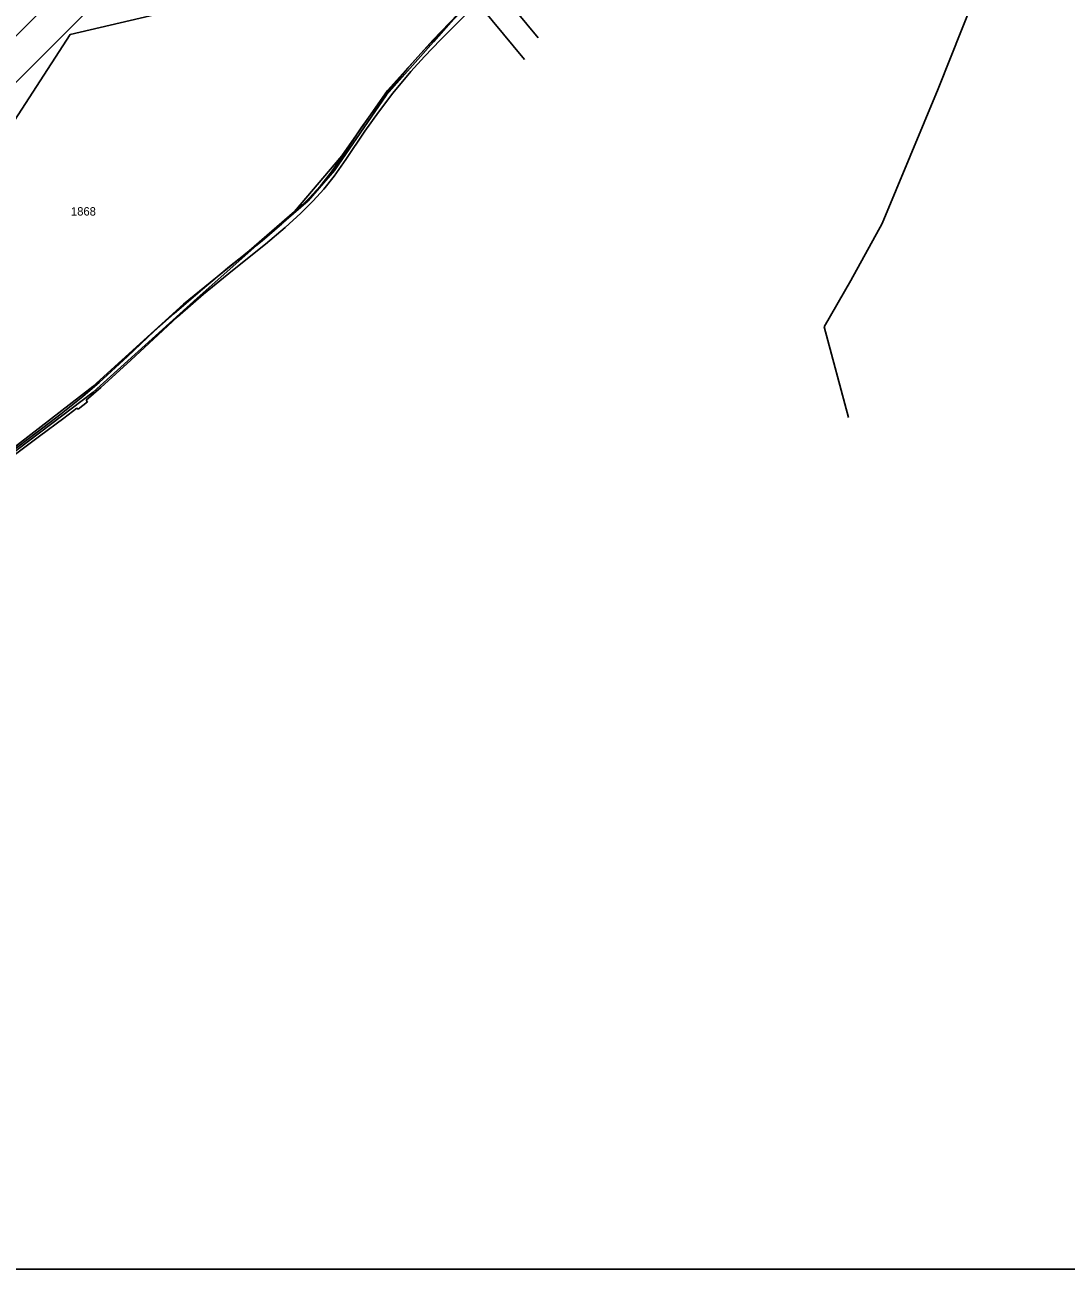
# Model space of a CAD drawing. Extents: x -564810 to -550519, y -1045831 to -1034011.
# Drawn here: x -552634 to -552001, y -1039636 to -1038879 of the extents above; entities that cross this region are included whole.
import ezdxf

# ---------------------------------------------------------------- set-up
doc = ezdxf.new("R2010")
doc.units = 0
for name, color, linetype in [('KN stav', 7, 'Continuous'), ('Obvod KPU', 7, 'Continuous'), ('Odvodněné plochy', 7, 'Continuous'), ('Parcelní čísla', 7, 'Continuous'), ('Plynovod', 7, 'Continuous'), ('Polní cesty stavající', 7, 'Continuous'), ('přeložka st silnice', 7, 'Continuous'), ('Vrstva 33', 7, 'Continuous'), ('Vrstva 63', 7, 'Continuous')]:
    doc.layers.add(name, color=color, linetype=linetype)

msp = doc.modelspace()

# ---------------------------------------------------------------- linework, layer by layer
at = {"layer": 'KN stav'}
for p, q in [((-552341.81, -1038838.89), (-552385.85, -1038888.91)), ((-552385.85, -1038888.91), (-552414.49, -1038921.28)), ((-552414.49, -1038921.28), (-552446.15, -1038967.21)), ((-552446.15, -1038967.21), (-552462.05, -1038985.67)), ((-552462.05, -1038985.67), (-552493.35, -1039012.79)), ((-552493.35, -1039012.79), (-552529.68, -1039045.03)), ((-552529.68, -1039045.03), (-552592.93, -1039102.29)), ((-552592.93, -1039102.29), (-552672.88, -1039162.55))]:
    msp.add_line(p, q, dxfattribs=at)
at = {"layer": 'Obvod KPU'}
for p, q in [((-552386.15, -1038887.74), (-552324.24, -1038823.4)), ((-552413.93, -1038918.67), (-552386.15, -1038887.74)), ((-552441.71, -1038958.32), (-552413.93, -1038918.67)), ((-552470.45, -1038992.31), (-552441.71, -1038958.32)), ((-552497.94, -1039016.18), (-552470.45, -1038992.31)), ((-552537.94, -1039048.57), (-552497.94, -1039016.18)), ((-552593.19, -1039098.67), (-552537.94, -1039048.57)), ((-552670.5, -1039158.57), (-552593.19, -1039098.67))]:
    msp.add_line(p, q, dxfattribs=at)
at = {"layer": 'Odvodněné plochy'}
msp.add_lwpolyline([(-552481.84, -1038855.09), (-552606.98, -1038884.54), (-552654.83, -1038958.17), (-552680.6, -1039015.24), (-552733.97, -1038945.29), (-552767.09, -1038873.49)], dxfattribs=at)
at = {"layer": 'Plynovod'}
for points in [[(-552322.24, -1038886.46), (-552991.86, -1038078.43), (-553130.06, -1037845.94), (-553165.24, -1037785.62), (-553212.98, -1037711.48), (-553233.08, -1037599.64), (-553457.96, -1037250.28), (-553542.14, -1037118.33), (-553569.78, -1036713.69), (-553743.15, -1036474.92), (-554047.18, -1036089.12), (-554447.95, -1035586.45)], [(-552330.5, -1038899.71), (-553000.12, -1038091.67), (-553138.32, -1037859.19), (-553173.5, -1037798.87), (-553221.24, -1037724.72), (-553241.34, -1037612.88), (-553466.22, -1037263.53), (-553550.4, -1037131.58), (-553578.03, -1036726.93), (-553751.41, -1036488.16), (-554055.44, -1036102.37), (-554456.21, -1035599.7)]]:
    msp.add_lwpolyline(points, dxfattribs=at)
at = {"layer": 'Polní cesty stavající'}
for p, q in [((-552366.93, -1038868.61), (-552383.34, -1038885.4)), ((-552381.57, -1038887.8), (-552364.73, -1038870.84)), ((-552383.34, -1038885.4), (-552393.52, -1038896.1)), ((-552391.32, -1038897.96), (-552381.57, -1038887.8)), ((-552393.52, -1038896.1), (-552401.67, -1038905.2)), ((-552399.61, -1038907), (-552391.32, -1038897.96)), ((-552401.67, -1038905.2), (-552412.93, -1038918.56)), ((-552410.7, -1038920.33), (-552399.61, -1038907)), ((-552412.93, -1038918.56), (-552421.66, -1038929.76)), ((-552419.4, -1038931.8), (-552410.7, -1038920.33)), ((-552421.66, -1038929.76), (-552429.89, -1038941.41)), ((-552427.57, -1038943.34), (-552419.4, -1038931.8)), ((-552429.89, -1038941.41), (-552441.7, -1038959.12)), ((-552439.17, -1038960.67), (-552427.57, -1038943.34)), ((-552441.7, -1038959.12), (-552448.58, -1038968.87)), ((-552446.25, -1038970.7), (-552439.17, -1038960.67)), ((-552448.58, -1038968.87), (-552454.68, -1038976.61)), ((-552452.51, -1038978.7), (-552446.25, -1038970.7)), ((-552454.68, -1038976.61), (-552461.53, -1038984.08)), ((-552458.99, -1038985.8), (-552452.51, -1038978.7)), ((-552461.53, -1038984.08), (-552469.13, -1038991.6)), ((-552466.62, -1038993.36), (-552458.99, -1038985.8)), ((-552469.13, -1038991.6), (-552478.19, -1038999.82)), ((-552476.1, -1039002), (-552466.62, -1038993.36)), ((-552478.19, -1038999.82), (-552490.07, -1039010.06)), ((-552488.16, -1039012.22), (-552476.1, -1039002)), ((-552490.07, -1039010.06), (-552509.94, -1039025.74)), ((-552508.25, -1039028.26), (-552488.16, -1039012.22)), ((-552509.94, -1039025.74), (-552527.66, -1039040.61)), ((-552525.81, -1039042.66), (-552508.25, -1039028.26)), ((-552527.66, -1039040.61), (-552543.73, -1039054.39)), ((-552541.64, -1039056.45), (-552525.81, -1039042.66)), ((-552543.73, -1039054.39), (-552555.78, -1039065.12)), ((-552553.46, -1039067.25), (-552541.64, -1039056.45)), ((-552555.78, -1039065.12), (-552572.14, -1039080.52)), ((-552570.09, -1039082.65), (-552553.46, -1039067.25)), ((-552572.14, -1039080.52), (-552589.35, -1039096.28)), ((-552588.22, -1039099.4), (-552570.09, -1039082.65)), ((-552589.35, -1039096.28), (-552599.27, -1039104.8)), ((-552597.24, -1039107.14), (-552588.22, -1039099.4)), ((-552599.27, -1039104.8), (-552612.42, -1039115.45)), ((-552602.04, -1039112.62), (-552596.48, -1039108.13)), ((-552596.48, -1039108.13), (-552597.24, -1039107.14)), ((-552612.42, -1039115.45), (-552627.1, -1039126.6)), ((-552610.72, -1039118.02), (-552602.79, -1039111.91)), ((-552602.79, -1039111.91), (-552602.04, -1039112.62)), ((-552625.52, -1039129.02), (-552610.72, -1039118.02)), ((-552627.1, -1039126.6), (-552650.74, -1039144.33)), ((-552649.06, -1039146.73), (-552625.52, -1039129.02))]:
    msp.add_line(p, q, dxfattribs=at)
at = {"layer": 'přeložka st silnice'}
for p, q in [((-552719.22, -1038964.62), (-552384.48, -1038629.88)), ((-552706.98, -1038980.66), (-552365.76, -1038639.45))]:
    msp.add_line(p, q, dxfattribs=at)
at = {"layer": 'Vrstva 33'}
msp.add_lwpolyline([(-551787.23, -1038465.89), (-551841.61, -1038535.13), (-551862.09, -1038525.24), (-551895.28, -1038529.48), (-551932.71, -1038561.98), (-551963.79, -1038590.24), (-551986.39, -1038616.38), (-552001.93, -1038648.88), (-552017.46, -1038661.6), (-552025.94, -1038676.44), (-552042.18, -1038708.23), (-552050.66, -1038749.21), (-552049.95, -1038793.94), (-552042.18, -1038825.03), (-552078.91, -1038917.59), (-552112.81, -1038999.55), (-552131.87, -1039034.17), (-552148.12, -1039062.43), (-552133.29, -1039117.54)], dxfattribs=at)
at = {"layer": 'Vrstva 63'}
msp.add_lwpolyline([(-550519.28, -1039635.94), (-556362.35, -1039635.94), (-556362.35, -1034682.32), (-550519.28, -1034682.32)], close=True, dxfattribs=at)

# ---------------------------------------------------------------- texts
at = {"layer": 'Parcelní čísla'}
msp.add_text('1868', height=5.1, dxfattribs=at).set_placement((-552606.44, -1038994.73))

doc.saveas('drawing.dxf')
